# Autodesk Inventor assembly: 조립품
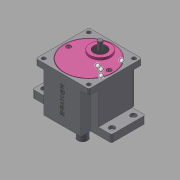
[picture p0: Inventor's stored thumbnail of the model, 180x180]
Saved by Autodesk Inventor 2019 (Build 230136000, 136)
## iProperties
Created: 2020-01
Part Number: 조립품
Material: 일반
Document SubType Name: Assembly
Designer: 323-17
Author: 323-17
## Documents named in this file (10)
- C:\Users\323-17\Desktop\700119V1005\조립품.iam
- C:\Users\323-17\Desktop\700119V1005\본체.ipt
- C:\Users\323-17\Desktop\700119V1005\서브 축.ipt
- C:\Users\323-17\Desktop\700119V1005\베어링 6003.ipt
- C:\Users\323-17\Desktop\700119V1005\베어링 608.ipt
- C:\Users\323-17\Desktop\700119V1005\메인 축.ipt
- C:\Users\323-17\Desktop\700119V1005\오일 실 17 32 8.ipt
- C:\Users\323-17\Desktop\700119V1005\커버.ipt
- C:\Users\323-17\Desktop\700119V1005\볼트 M4.ipt
- C:\Users\323-17\Desktop\700119V1005\오일 실 8 22 7.ipt
